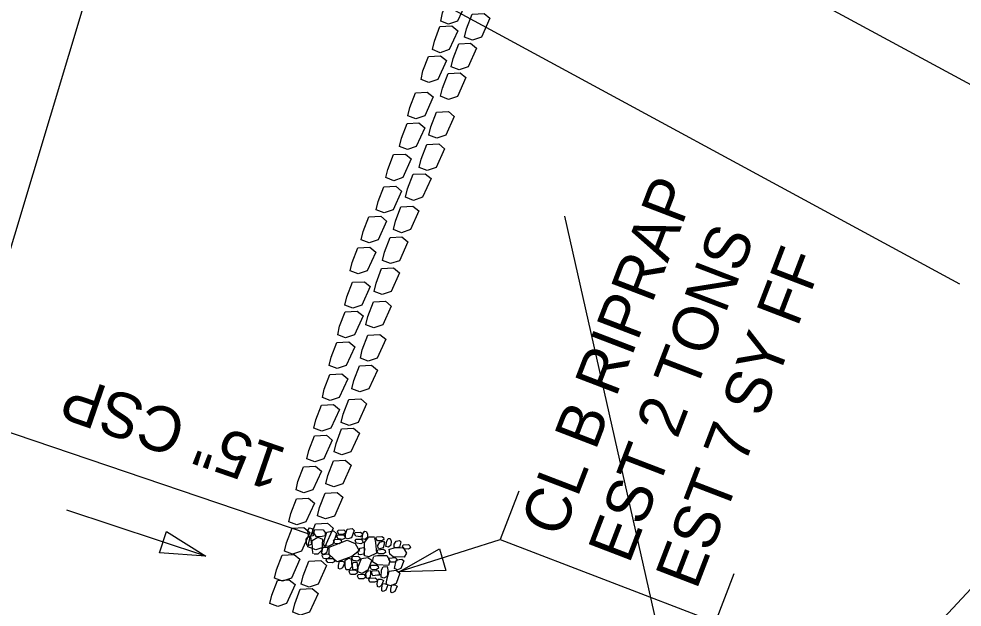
# Model space of a CAD drawing. Extents: x 2384780 to 2405432, y 547869 to 573706.
# Drawn here: x 2400272 to 2400376.6, y 562480.9 to 562546.1 of the extents above; entities that cross this region are included whole.
import ezdxf

# ---------------------------------------------------------------- set-up
doc = ezdxf.new("R2010")
doc.units = 0
for name, color, linetype in [('Old_Level_1', 7, 'Continuous'), ('Old_Level_20', 7, 'Continuous'), ('Old_Level_5', 7, 'Continuous'), ('Old_Level_62', 7, 'Continuous'), ('Old_Level_63', 7, 'Continuous'), ('Prop Buffer Zone 1', 7, 'Continuous'), ('Prop Buffer Zone 2', 7, 'Continuous')]:
    doc.layers.add(name, color=color, linetype=linetype)

msp = doc.modelspace()

# ---------------------------------------------------------------- linework, layer by layer
at = {"layer": 'Old_Level_1'}
for q in [(2400318.08, 562676.77), (2400304.14, 562489)]:
    msp.add_line((2400265.51, 562502.09), q, dxfattribs=at)
for points in [[(2400304.53, 562489.57), (2400304.55, 562489.33), (2400304.61, 562488.76), (2400304.28, 562488.71), (2400304.1, 562488.75), (2400304.03, 562489.36), (2400304.24, 562489.65), (2400304.53, 562489.57)], [(2400305.97, 562488.79), (2400305.63, 562488.7), (2400305, 562488.65), (2400304.7, 562489.1), (2400304.8, 562489.49), (2400305.73, 562489.42), (2400305.96, 562489.15), (2400305.97, 562488.79)], [(2400308.22, 562489.09), (2400307.98, 562488.92), (2400307.48, 562488.96), (2400307.32, 562489.23), (2400307.41, 562489.4), (2400308.01, 562489.42), (2400308.17, 562489.3), (2400308.22, 562489.09)], [(2400308.21, 562488.52), (2400308.21, 562488.94), (2400308.38, 562489.51), (2400308.94, 562489.59), (2400309.19, 562489.35), (2400308.86, 562488.55), (2400308.48, 562488.43), (2400308.21, 562488.52)], [(2400304.37, 562488.56), (2400304.38, 562488.34), (2400304.46, 562487.8), (2400304.12, 562487.69), (2400303.94, 562487.75), (2400303.85, 562488.41), (2400304.08, 562488.65), (2400304.37, 562488.56)], [(2400304.61, 562486.78), (2400304.55, 562487.22), (2400304.53, 562488.25), (2400305.15, 562488.62), (2400305.65, 562488.42), (2400305.59, 562487.19), (2400305.14, 562486.73), (2400304.73, 562486.74)], [(2400305.82, 562487.71), (2400305.85, 562488.21), (2400306.13, 562489.19), (2400306.88, 562489.33), (2400307.22, 562489.03), (2400306.8, 562487.86), (2400306.28, 562487.59), (2400305.82, 562487.71)], [(2400307.78, 562488.06), (2400307.54, 562487.9), (2400307.04, 562487.94), (2400306.88, 562488.2), (2400306.97, 562488.37), (2400307.57, 562488.41), (2400307.73, 562488.28), (2400307.78, 562488.06)], [(2400308.18, 562488.5), (2400307.89, 562488.36), (2400307.42, 562488.43), (2400307.25, 562488.66), (2400307.31, 562488.88), (2400307.98, 562488.88), (2400308.13, 562488.71), (2400308.18, 562488.5)], [(2400310.1, 562488.84), (2400309.86, 562488.68), (2400309.36, 562488.72), (2400309.2, 562488.98), (2400309.3, 562489.15), (2400309.89, 562489.18), (2400310.04, 562489.06), (2400310.1, 562488.84)], [(2400310.16, 562488.02), (2400309.92, 562487.89), (2400309.44, 562487.95), (2400309.27, 562488.2), (2400309.34, 562488.41), (2400309.97, 562488.4), (2400310.11, 562488.23), (2400310.16, 562488.02)], [(2400310.52, 562489.25), (2400310.64, 562489.01), (2400310.64, 562488.58), (2400310.37, 562488.35), (2400310.06, 562488.44), (2400310.15, 562489.03), (2400310.34, 562489.29), (2400310.52, 562489.25)], [(2400311.41, 562488.55), (2400311.54, 562488.02), (2400311.66, 562486.84), (2400310.8, 562486.43), (2400310.33, 562486.57), (2400310.33, 562488.05), (2400310.8, 562488.65), (2400311.44, 562488.67)], [(2400312.47, 562488.37), (2400312.23, 562488.2), (2400311.74, 562488.23), (2400311.57, 562488.5), (2400311.66, 562488.66), (2400312.25, 562488.7), (2400312.41, 562488.59), (2400312.47, 562488.37)], [(2400313.15, 562488.48), (2400313.29, 562488.17), (2400313.24, 562487.72), (2400312.99, 562487.51), (2400312.7, 562487.59), (2400312.8, 562488.19), (2400312.95, 562488.46), (2400313.15, 562488.48)], [(2400305.57, 562486.85), (2400305.63, 562487.06), (2400305.75, 562487.5), (2400306.07, 562487.53), (2400306.25, 562487.47), (2400306.09, 562486.89), (2400305.79, 562486.67), (2400305.57, 562486.85)], [(2400309.59, 562487.01), (2400308.93, 562486.47), (2400307.29, 562485.89), (2400306.39, 562486.69), (2400306.39, 562487.52), (2400308.4, 562488.3), (2400309.3, 562487.91), (2400309.75, 562487.08)], [(2400309.64, 562486.7), (2400309.61, 562487.03), (2400309.83, 562487.39), (2400310.21, 562487.48), (2400310.36, 562487.32), (2400310.19, 562486.74), (2400309.82, 562486.65), (2400309.64, 562486.7)], [(2400311.84, 562487.39), (2400311.81, 562487.71), (2400312.03, 562488.08), (2400312.41, 562488.17), (2400312.55, 562488), (2400312.39, 562487.43), (2400312.02, 562487.33), (2400311.84, 562487.39)], [(2400313.11, 562487.28), (2400313.59, 562487.46), (2400314.61, 562487.47), (2400314.99, 562486.86), (2400314.72, 562486.39), (2400313.49, 562486.43), (2400313.11, 562486.74), (2400313.04, 562487.3)], [(2400313.62, 562487.51), (2400313.6, 562487.83), (2400313.82, 562488.19), (2400314.2, 562488.27), (2400314.34, 562488.11), (2400314.18, 562487.53), (2400313.8, 562487.45), (2400313.62, 562487.51)], [(2400315.42, 562487.45), (2400315.18, 562487.28), (2400314.68, 562487.32), (2400314.52, 562487.59), (2400314.61, 562487.76), (2400315.2, 562487.8), (2400315.36, 562487.67), (2400315.42, 562487.45)], [(2400306.49, 562486.4), (2400306.26, 562486.24), (2400305.76, 562486.26), (2400305.61, 562486.55), (2400305.67, 562486.72), (2400306.29, 562486.76), (2400306.48, 562486.6), (2400306.49, 562486.4)], [(2400307.02, 562485.91), (2400306.74, 562485.78), (2400306.24, 562485.81), (2400306.08, 562486.06), (2400306.15, 562486.27), (2400306.81, 562486.27), (2400306.97, 562486.12), (2400307.02, 562485.91)], [(2400308.3, 562485.02), (2400308.17, 562485.36), (2400308.17, 562486.07), (2400308.56, 562486.3), (2400308.84, 562486.21), (2400308.91, 562485.34), (2400308.62, 562485.02), (2400308.3, 562485.02)], [(2400309.8, 562486.13), (2400309.58, 562485.96), (2400309.08, 562486.03), (2400308.91, 562486.27), (2400308.98, 562486.48), (2400309.61, 562486.51), (2400309.79, 562486.33), (2400309.8, 562486.13)], [(2400309.58, 562484.79), (2400309.63, 562485.32), (2400310, 562486.26), (2400310.67, 562486.38), (2400311.12, 562486.07), (2400310.69, 562484.95), (2400310.06, 562484.58), (2400309.58, 562484.79)], [(2400311.3, 562486.52), (2400311.74, 562486.58), (2400312.8, 562486.59), (2400313.13, 562485.99), (2400312.98, 562485.48), (2400311.76, 562485.57), (2400311.22, 562485.88), (2400311.3, 562486.4)], [(2400312.64, 562486.91), (2400312.43, 562486.78), (2400311.87, 562486.78), (2400311.72, 562487.06), (2400311.81, 562487.23), (2400312.44, 562487.28), (2400312.6, 562487.16), (2400312.64, 562486.91)], [(2400313.9, 562485.99), (2400313.65, 562485.84), (2400313.15, 562485.85), (2400313, 562486.13), (2400313.06, 562486.31), (2400313.7, 562486.36), (2400313.89, 562486.2), (2400313.9, 562485.99)], [(2400307.44, 562485.16), (2400307.45, 562485.47), (2400307.54, 562485.95), (2400307.9, 562485.96), (2400308.13, 562485.82), (2400307.88, 562485.23), (2400307.61, 562485.08), (2400307.44, 562485.16)], [(2400309.46, 562485.86), (2400309.5, 562485.62), (2400309.56, 562485.09), (2400309.19, 562485), (2400309.03, 562485.05), (2400308.98, 562485.69), (2400309.14, 562485.84), (2400309.46, 562485.86)], [(2400311.87, 562485.18), (2400311.6, 562485.01), (2400311.1, 562485.05), (2400310.95, 562485.34), (2400311.04, 562485.51), (2400311.63, 562485.53), (2400311.82, 562485.39), (2400311.87, 562485.18)], [(2400312.84, 562485.37), (2400312.92, 562484.99), (2400312.83, 562484.27), (2400312.46, 562484.08), (2400312.17, 562484.17), (2400312.19, 562485.01), (2400312.4, 562485.34), (2400312.84, 562485.37)], [(2400313.66, 562485.14), (2400313.7, 562485.51), (2400313.87, 562486.12), (2400314.44, 562486.17), (2400314.69, 562486.01), (2400314.33, 562485.14), (2400313.97, 562485), (2400313.66, 562485.14)], [(2400309.5, 562484.64), (2400309.27, 562484.48), (2400308.77, 562484.5), (2400308.62, 562484.79), (2400308.68, 562484.96), (2400309.31, 562485.01), (2400309.49, 562484.84), (2400309.5, 562484.64)], [(2400310.43, 562484.15), (2400310.19, 562483.99), (2400309.69, 562484.02), (2400309.54, 562484.3), (2400309.6, 562484.48), (2400310.23, 562484.53), (2400310.41, 562484.35), (2400310.43, 562484.15)], [(2400310.98, 562484.91), (2400310.99, 562484.68), (2400310.95, 562484.18), (2400310.68, 562484.03), (2400310.53, 562484.07), (2400310.45, 562484.6), (2400310.65, 562484.86), (2400310.86, 562484.91)], [(2400311.97, 562484.41), (2400311.77, 562484.4), (2400311.24, 562484.34), (2400311.11, 562484.7), (2400311.16, 562484.88), (2400311.84, 562484.91), (2400311.93, 562484.66), (2400311.97, 562484.41)], [(2400312.72, 562483.38), (2400312.79, 562483.89), (2400313.04, 562484.84), (2400313.82, 562484.97), (2400314.22, 562484.62), (2400313.81, 562483.49), (2400313.23, 562483.23), (2400312.72, 562483.38)], [(2400311.74, 562483.74), (2400311.43, 562483.63), (2400310.92, 562483.63), (2400310.81, 562483.9), (2400310.86, 562484.07), (2400311.5, 562484.13), (2400311.69, 562483.95), (2400311.74, 562483.74)], [(2400311.74, 562483.15), (2400311.73, 562483.47), (2400311.83, 562483.95), (2400312.18, 562483.95), (2400312.42, 562483.81), (2400312.16, 562483.22), (2400311.89, 562483.07), (2400311.74, 562483.15)], [(2400312.23, 562482.67), (2400312.23, 562482.98), (2400312.33, 562483.46), (2400312.69, 562483.47), (2400312.92, 562483.33), (2400312.67, 562482.74), (2400312.4, 562482.59), (2400312.23, 562482.67)], [(2400313.23, 562482.52), (2400313.23, 562482.84), (2400313.33, 562483.32), (2400313.69, 562483.32), (2400313.92, 562483.18), (2400313.67, 562482.59), (2400313.4, 562482.44), (2400313.23, 562482.52)]]:
    msp.add_lwpolyline(points, dxfattribs=at)
at = {"layer": 'Old_Level_20'}
for points in [[(2400318.76, 562545.86), (2400318.98, 562546.78), (2400319.6, 562548.4), (2400320.93, 562548.47), (2400321.58, 562547.94), (2400320.64, 562545.85), (2400319.64, 562545.52), (2400318.76, 562545.86)], [(2400321.41, 562544.09), (2400321.62, 562545.02), (2400322.25, 562546.64), (2400323.57, 562546.71), (2400324.22, 562546.17), (2400323.28, 562544.09), (2400322.29, 562543.76), (2400321.41, 562544.09)], [(2400317.84, 562542.7), (2400318.06, 562543.62), (2400318.68, 562545.25), (2400320, 562545.32), (2400320.65, 562544.78), (2400319.71, 562542.7), (2400318.72, 562542.36), (2400317.84, 562542.7)], [(2400319.92, 562540.78), (2400320.14, 562541.71), (2400320.76, 562543.33), (2400322.08, 562543.4), (2400322.73, 562542.86), (2400321.8, 562540.78), (2400320.8, 562540.44), (2400319.92, 562540.78)], [(2400316.58, 562539.4), (2400316.8, 562540.33), (2400317.42, 562541.95), (2400318.74, 562542.02), (2400319.39, 562541.48), (2400318.46, 562539.4), (2400317.46, 562539.07), (2400316.58, 562539.4)], [(2400318.75, 562537.52), (2400318.97, 562538.44), (2400319.59, 562540.06), (2400320.91, 562540.13), (2400321.56, 562539.6), (2400320.63, 562537.51), (2400319.63, 562537.18), (2400318.75, 562537.52)], [(2400315.12, 562535.37), (2400315.33, 562536.29), (2400315.96, 562537.92), (2400317.28, 562537.99), (2400317.93, 562537.45), (2400316.99, 562535.37), (2400315.99, 562535.03), (2400315.12, 562535.37)], [(2400317.45, 562533.2), (2400317.67, 562534.13), (2400318.29, 562535.75), (2400319.61, 562535.82), (2400320.26, 562535.28), (2400319.33, 562533.2), (2400318.33, 562532.86), (2400317.45, 562533.2)], [(2400314.19, 562531.95), (2400314.41, 562532.88), (2400315.03, 562534.5), (2400316.35, 562534.57), (2400317, 562534.03), (2400316.06, 562531.95), (2400315.07, 562531.62), (2400314.19, 562531.95)], [(2400316.39, 562529.63), (2400316.61, 562530.56), (2400317.23, 562532.18), (2400318.55, 562532.25), (2400319.2, 562531.71), (2400318.26, 562529.63), (2400317.27, 562529.29), (2400316.39, 562529.63)], [(2400312.68, 562528.5), (2400312.9, 562529.42), (2400313.52, 562531.05), (2400314.85, 562531.12), (2400315.5, 562530.58), (2400314.56, 562528.5), (2400313.56, 562528.16), (2400312.68, 562528.5)], [(2400314.87, 562526.32), (2400315.09, 562527.25), (2400315.71, 562528.87), (2400317.04, 562528.94), (2400317.69, 562528.4), (2400316.75, 562526.32), (2400315.75, 562525.98), (2400314.87, 562526.32)], [(2400311.62, 562524.93), (2400311.84, 562525.85), (2400312.46, 562527.48), (2400313.78, 562527.55), (2400314.43, 562527.01), (2400313.5, 562524.93), (2400312.5, 562524.59), (2400311.62, 562524.93)], [(2400313.52, 562522.73), (2400313.74, 562523.66), (2400314.36, 562525.28), (2400315.69, 562525.35), (2400316.34, 562524.81), (2400315.4, 562522.73), (2400314.4, 562522.39), (2400313.52, 562522.73)], [(2400309.96, 562521.61), (2400310.18, 562522.53), (2400310.8, 562524.16), (2400312.12, 562524.23), (2400312.77, 562523.69), (2400311.84, 562521.61), (2400310.84, 562521.27), (2400309.96, 562521.61)], [(2400312.31, 562519.3), (2400312.52, 562520.22), (2400313.15, 562521.85), (2400314.47, 562521.92), (2400315.12, 562521.38), (2400314.18, 562519.29), (2400313.19, 562518.96), (2400312.31, 562519.3)], [(2400308.74, 562518.17), (2400308.96, 562519.1), (2400309.58, 562520.72), (2400310.91, 562520.79), (2400311.56, 562520.25), (2400310.62, 562518.17), (2400309.62, 562517.84), (2400308.74, 562518.17)], [(2400311.38, 562515.88), (2400311.6, 562516.81), (2400312.22, 562518.43), (2400313.54, 562518.5), (2400314.19, 562517.96), (2400313.26, 562515.88), (2400312.26, 562515.55), (2400311.38, 562515.88)], [(2400308.14, 562514.34), (2400308.35, 562515.27), (2400308.98, 562516.89), (2400310.3, 562516.96), (2400310.95, 562516.42), (2400310.01, 562514.34), (2400309.02, 562514.01), (2400308.14, 562514.34)], [(2400310.47, 562512.18), (2400310.69, 562513.1), (2400311.31, 562514.73), (2400312.64, 562514.8), (2400313.29, 562514.26), (2400312.35, 562512.18), (2400311.35, 562511.84), (2400310.47, 562512.18)], [(2400307.35, 562511.08), (2400307.56, 562512.01), (2400308.19, 562513.63), (2400309.51, 562513.7), (2400310.16, 562513.17), (2400309.22, 562511.08), (2400308.22, 562510.75), (2400307.35, 562511.08)], [(2400306.42, 562507.67), (2400306.64, 562508.59), (2400307.26, 562510.22), (2400308.58, 562510.29), (2400309.23, 562509.75), (2400308.29, 562507.67), (2400307.3, 562507.33), (2400306.42, 562507.67)], [(2400309.86, 562508.49), (2400310.07, 562509.42), (2400310.7, 562511.04), (2400312.02, 562511.11), (2400312.67, 562510.57), (2400311.73, 562508.49), (2400310.74, 562508.16), (2400309.86, 562508.49)], [(2400308.93, 562505.08), (2400309.15, 562506), (2400309.77, 562507.63), (2400311.09, 562507.7), (2400311.74, 562507.16), (2400310.81, 562505.08), (2400309.81, 562504.74), (2400308.93, 562505.08)], [(2400305.65, 562504.12), (2400305.86, 562505.05), (2400306.49, 562506.67), (2400307.81, 562506.74), (2400308.46, 562506.2), (2400307.52, 562504.12), (2400306.53, 562503.78), (2400305.65, 562504.12)], [(2400304.72, 562500.71), (2400304.94, 562501.63), (2400305.56, 562503.26), (2400306.89, 562503.33), (2400307.54, 562502.79), (2400306.6, 562500.7), (2400305.6, 562500.37), (2400304.72, 562500.71)], [(2400307.74, 562501.35), (2400307.95, 562502.28), (2400308.58, 562503.9), (2400309.9, 562503.97), (2400310.55, 562503.43), (2400309.61, 562501.35), (2400308.61, 562501.02), (2400307.74, 562501.35)], [(2400303.94, 562497.3), (2400304.16, 562498.23), (2400304.78, 562499.85), (2400306.1, 562499.92), (2400306.75, 562499.38), (2400305.82, 562497.3), (2400304.82, 562496.97), (2400303.94, 562497.3)], [(2400306.94, 562498.09), (2400307.16, 562499.02), (2400307.78, 562500.64), (2400309.11, 562500.71), (2400309.76, 562500.17), (2400308.82, 562498.09), (2400307.82, 562497.76), (2400306.94, 562498.09)], [(2400306.03, 562494.53), (2400306.24, 562495.46), (2400306.87, 562497.08), (2400308.19, 562497.15), (2400308.84, 562496.62), (2400307.9, 562494.53), (2400306.91, 562494.2), (2400306.03, 562494.53)], [(2400302.73, 562493.87), (2400302.94, 562494.79), (2400303.56, 562496.42), (2400304.89, 562496.49), (2400305.54, 562495.95), (2400304.6, 562493.87), (2400303.6, 562493.53), (2400302.73, 562493.87)], [(2400305.11, 562490.98), (2400305.33, 562491.9), (2400305.95, 562493.52), (2400307.27, 562493.59), (2400307.92, 562493.06), (2400306.99, 562490.97), (2400305.99, 562490.64), (2400305.11, 562490.98)], [(2400327.42, 562493.74), (2400325.35, 562488.36), (2400349.21, 562479.2), (2400351.28, 562484.58)], [(2400301.95, 562490.32), (2400302.17, 562491.24), (2400302.79, 562492.87), (2400304.12, 562492.94), (2400304.77, 562492.4), (2400303.83, 562490.32), (2400302.83, 562489.98), (2400301.95, 562490.32)], [(2400301.45, 562487.08), (2400301.67, 562488), (2400302.29, 562489.63), (2400303.61, 562489.7), (2400304.26, 562489.16), (2400303.33, 562487.08), (2400302.33, 562486.74), (2400301.45, 562487.08)], [(2400304.04, 562487.55), (2400304.26, 562488.48), (2400304.88, 562490.1), (2400306.2, 562490.17), (2400306.85, 562489.63), (2400305.91, 562487.55), (2400304.92, 562487.21), (2400304.04, 562487.55)], [(2400300.35, 562484.09), (2400300.57, 562485.01), (2400301.19, 562486.64), (2400302.51, 562486.71), (2400303.16, 562486.17), (2400302.22, 562484.09), (2400301.23, 562483.75), (2400300.35, 562484.09)], [(2400303.31, 562483.42), (2400303.53, 562484.35), (2400304.15, 562485.97), (2400305.47, 562486.04), (2400306.12, 562485.5), (2400305.18, 562483.42), (2400304.19, 562483.08), (2400303.31, 562483.42)], [(2400299.82, 562481.28), (2400300.03, 562482.21), (2400300.66, 562483.83), (2400301.98, 562483.9), (2400302.63, 562483.36), (2400301.69, 562481.28), (2400300.7, 562480.95), (2400299.82, 562481.28)], [(2400302.36, 562480.3), (2400302.58, 562481.22), (2400303.2, 562482.85), (2400304.53, 562482.92), (2400305.18, 562482.38), (2400304.24, 562480.3), (2400303.24, 562479.96), (2400302.36, 562480.3)]]:
    msp.add_lwpolyline(points, dxfattribs=at)
at = {"layer": 'Old_Level_5'}
for p, q in [((2400292.74, 562486.51), (2400277.33, 562491.62)), ((2400314.17, 562484.82), (2400325.35, 562488.36))]:
    msp.add_line(p, q, dxfattribs=at)
for points in [[(2400288.39, 562489.27), (2400292.74, 562486.51), (2400287.6, 562486.9)], [(2400319.32, 562484.92), (2400314.17, 562484.77), (2400318.64, 562487.33)]]:
    msp.add_lwpolyline(points, close=True, dxfattribs=at)
at = {"layer": 'Old_Level_62'}
msp.add_lwpolyline([(2400332.48, 562524.22), (2400347.64, 562456.97), (2400355.91, 562431.05), (2400375.5, 562357.55), (2400393.58, 562280.09), (2400434.7, 562191.5), (2400592.87, 562087.56)], dxfattribs=at)
at = {"layer": 'Old_Level_63'}
msp.add_circle((2400238.44, 562609.29), 187.94, dxfattribs=at)
at = {"layer": 'Prop Buffer Zone 1'}
msp.add_line((2400387.85, 562533.17), (2400314.31, 562573.07), dxfattribs=at)
at = {"layer": 'Prop Buffer Zone 2'}
msp.add_line((2400376.29, 562516.69), (2400310.96, 562552.14), dxfattribs=at)

# ---------------------------------------------------------------- texts
at = {"layer": 'Old_Level_1'}
for s, rotation, p in [('CL B RIPRAP', 68.9999, (2400332.18, 562488.42)), ('EST 2 TONS', 68.9999, (2400339.64, 562485.55)), ('EST 7 SY FF', 68.9999, (2400347.11, 562482.68)), ('15" CSP', 160.9579, (2400301.89, 562498.38))]:
    msp.add_text(s, height=5, rotation=rotation, dxfattribs=at).set_placement(p)

doc.saveas('drawing.dxf')
